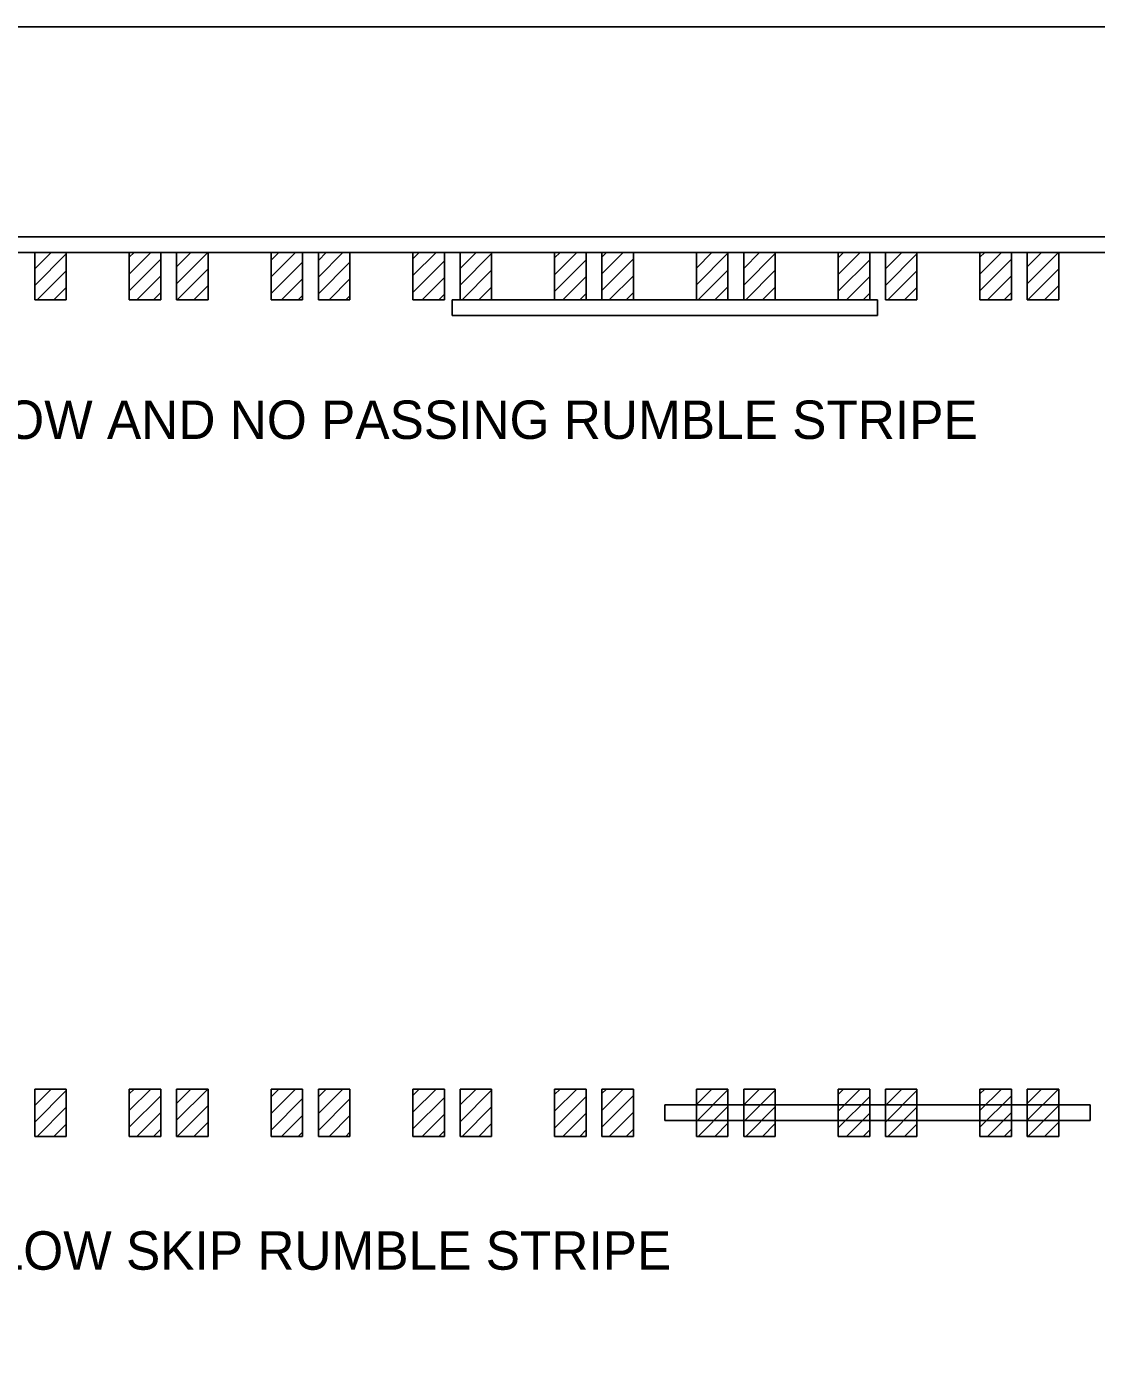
# Model space of a CAD drawing. Extents: x 49976.2 to 50021, y 49987.6 to 50011.4.
# Drawn here: x 50007.619 to 50009.846, y 49996.199 to 49998.999 of the extents above; entities that cross this region are included whole.
import ezdxf

# ---------------------------------------------------------------- set-up
doc = ezdxf.new("R2010")
doc.units = 0
doc.layers.add('Level 1', color=7, linetype='Continuous')
doc.layers.add('Level 2', color=7, linetype='Continuous')

msp = doc.modelspace()

# ---------------------------------------------------------------- linework, layer by layer
at = {"layer": 'Level 1'}
for p, q in [((50004.4031, 49998.5623), (50012.0505, 49998.5623)), ((50004.4031, 49998.5296), (50012.0505, 49998.5296)), ((50007.6358, 49998.4311), (50007.6358, 49998.5296)), ((50007.6358, 49998.5296), (50007.7014, 49998.5296)), ((50007.6358, 49998.4956), (50007.6697, 49998.5296)), ((50007.6358, 49998.4609), (50007.7014, 49998.5265)), ((50007.7014, 49998.5296), (50007.7014, 49998.4311)), ((50007.8326, 49998.4311), (50007.8326, 49998.5296)), ((50007.8326, 49998.5296), (50007.8982, 49998.5296)), ((50007.8326, 49998.4848), (50007.8773, 49998.5296)), ((50007.8326, 49998.5196), (50007.8425, 49998.5296)), ((50007.8326, 49998.45), (50007.8982, 49998.5156)), ((50007.8982, 49998.5296), (50007.8982, 49998.4311)), ((50007.931, 49998.4311), (50007.931, 49998.5296)), ((50007.931, 49998.5296), (50007.9966, 49998.5296)), ((50007.931, 49998.4647), (50007.9959, 49998.5296)), ((50007.931, 49998.4995), (50007.9611, 49998.5296)), ((50007.9966, 49998.5296), (50007.9966, 49998.4311)), ((50008.1278, 49998.4311), (50008.1278, 49998.5296)), ((50008.1278, 49998.5296), (50008.1934, 49998.5296)), ((50008.1278, 49998.4788), (50008.1786, 49998.5296)), ((50008.1278, 49998.5136), (50008.1438, 49998.5296)), ((50008.1278, 49998.444), (50008.1934, 49998.5096)), ((50008.1934, 49998.5296), (50008.1934, 49998.4311)), ((50008.2263, 49998.4311), (50008.2263, 49998.5296)), ((50008.2263, 49998.5296), (50008.2919, 49998.5296)), ((50008.2263, 49998.4784), (50008.2774, 49998.5296)), ((50008.2263, 49998.5132), (50008.2426, 49998.5296)), ((50008.2263, 49998.4436), (50008.2919, 49998.5092)), ((50008.2919, 49998.5296), (50008.2919, 49998.4311)), ((50008.4231, 49998.4311), (50008.4231, 49998.5296)), ((50008.4231, 49998.5296), (50008.4887, 49998.5296)), ((50008.4231, 49998.4814), (50008.4713, 49998.5296)), ((50008.4231, 49998.5162), (50008.4365, 49998.5296)), ((50008.4231, 49998.4466), (50008.4887, 49998.5122)), ((50008.4887, 49998.5296), (50008.4887, 49998.4311)), ((50008.5215, 49998.4311), (50008.5215, 49998.5296)), ((50008.5215, 49998.5296), (50008.5871, 49998.5296)), ((50008.5215, 49998.4965), (50008.5546, 49998.5296)), ((50008.5215, 49998.4617), (50008.5871, 49998.5273)), ((50008.5871, 49998.5296), (50008.5871, 49998.4311)), ((50008.7183, 49998.4311), (50008.7183, 49998.5296)), ((50008.7183, 49998.5296), (50008.7839, 49998.5296)), ((50008.7183, 49998.4834), (50008.7645, 49998.5296)), ((50008.7183, 49998.5182), (50008.7297, 49998.5296)), ((50008.7183, 49998.4486), (50008.7839, 49998.5142)), ((50008.7839, 49998.5296), (50008.7839, 49998.4311)), ((50008.8167, 49998.4311), (50008.8167, 49998.5296)), ((50008.8167, 49998.5296), (50008.8824, 49998.5296)), ((50008.8167, 49998.4853), (50008.861, 49998.5296)), ((50008.8167, 49998.5201), (50008.8262, 49998.5296)), ((50008.8167, 49998.4505), (50008.8824, 49998.5161)), ((50008.8824, 49998.5296), (50008.8824, 49998.4311)), ((50009.0136, 49998.4311), (50009.0136, 49998.5296)), ((50009.0136, 49998.5296), (50009.0792, 49998.5296)), ((50009.0136, 49998.4971), (50009.046, 49998.5296)), ((50009.0136, 49998.4623), (50009.0792, 49998.5279)), ((50009.0792, 49998.5296), (50009.0792, 49998.4311)), ((50009.112, 49998.4311), (50009.112, 49998.5296)), ((50009.112, 49998.5296), (50009.1776, 49998.5296)), ((50009.112, 49998.4965), (50009.145, 49998.5296)), ((50009.112, 49998.4617), (50009.1776, 49998.5273)), ((50009.1776, 49998.5296), (50009.1776, 49998.4311)), ((50009.3088, 49998.4311), (50009.3088, 49998.5296)), ((50009.3088, 49998.5296), (50009.3744, 49998.5296)), ((50009.3088, 49998.4837), (50009.3547, 49998.5296)), ((50009.3088, 49998.5185), (50009.3199, 49998.5296)), ((50009.3088, 49998.4489), (50009.3744, 49998.5145)), ((50009.3744, 49998.5296), (50009.3744, 49998.4311)), ((50009.4072, 49998.4311), (50009.4072, 49998.5296)), ((50009.4072, 49998.5296), (50009.4728, 49998.5296)), ((50009.4072, 49998.4956), (50009.4411, 49998.5296)), ((50009.4072, 49998.4609), (50009.4728, 49998.5265)), ((50009.4728, 49998.5296), (50009.4728, 49998.4311)), ((50009.6041, 49998.4311), (50009.6041, 49998.5296)), ((50009.6041, 49998.5296), (50009.6697, 49998.5296)), ((50009.6041, 49998.4848), (50009.6488, 49998.5296)), ((50009.6041, 49998.5196), (50009.614, 49998.5296)), ((50009.6041, 49998.45), (50009.6697, 49998.5156)), ((50009.6697, 49998.5296), (50009.6697, 49998.4311)), ((50009.7025, 49998.4311), (50009.7025, 49998.5296)), ((50009.7025, 49998.5296), (50009.7681, 49998.5296)), ((50009.7025, 49998.4647), (50009.7673, 49998.5296)), ((50009.7025, 49998.4995), (50009.7325, 49998.5296)), ((50009.7681, 49998.5296), (50009.7681, 49998.4311)), ((50007.6409, 49998.4311), (50007.7014, 49998.4917)), ((50007.8485, 49998.4311), (50007.8982, 49998.4808)), ((50007.9322, 49998.4311), (50007.9966, 49998.4955)), ((50008.1498, 49998.4311), (50008.1934, 49998.4748)), ((50008.2486, 49998.4311), (50008.2919, 49998.4745)), ((50008.4424, 49998.4311), (50008.4887, 49998.4774)), ((50008.5258, 49998.4311), (50008.5871, 49998.4925)), ((50008.7357, 49998.4311), (50008.7839, 49998.4794)), ((50008.8322, 49998.4311), (50008.8824, 49998.4813)), ((50009.0172, 49998.4311), (50009.0792, 49998.4931)), ((50009.1162, 49998.4311), (50009.1776, 49998.4925)), ((50009.3259, 49998.4311), (50009.3744, 49998.4797)), ((50009.4123, 49998.4311), (50009.4728, 49998.4917)), ((50009.62, 49998.4311), (50009.6697, 49998.4808)), ((50009.7037, 49998.4311), (50009.7681, 49998.4955)), ((50007.6756, 49998.4311), (50007.7014, 49998.4569)), ((50007.8833, 49998.4311), (50007.8982, 49998.4461)), ((50007.967, 49998.4311), (50007.9966, 49998.4607)), ((50008.5606, 49998.4311), (50008.5871, 49998.4577)), ((50008.867, 49998.4311), (50008.8824, 49998.4465)), ((50009.052, 49998.4311), (50009.0792, 49998.4583)), ((50009.151, 49998.4311), (50009.1776, 49998.4577)), ((50009.4471, 49998.4311), (50009.4728, 49998.4569)), ((50009.6548, 49998.4311), (50009.6697, 49998.4461)), ((50009.7385, 49998.4311), (50009.7681, 49998.4607)), ((50007.7014, 49998.4311), (50007.6358, 49998.4311)), ((50007.8982, 49998.4311), (50007.8326, 49998.4311)), ((50007.9966, 49998.4311), (50007.931, 49998.4311)), ((50008.1934, 49998.4311), (50008.1278, 49998.4311)), ((50008.1846, 49998.4311), (50008.1934, 49998.44)), ((50008.2919, 49998.4311), (50008.2263, 49998.4311)), ((50008.2834, 49998.4311), (50008.2919, 49998.4397)), ((50008.4887, 49998.4311), (50008.4231, 49998.4311)), ((50008.4772, 49998.4311), (50008.4887, 49998.4426)), ((50008.5051, 49998.4311), (50009.3908, 49998.4311)), ((50008.5051, 49998.4311), (50008.5051, 49998.3984)), ((50008.5871, 49998.4311), (50008.5215, 49998.4311)), ((50008.7839, 49998.4311), (50008.7183, 49998.4311)), ((50008.7705, 49998.4311), (50008.7839, 49998.4446)), ((50008.8824, 49998.4311), (50008.8167, 49998.4311)), ((50009.0792, 49998.4311), (50009.0136, 49998.4311)), ((50009.1776, 49998.4311), (50009.112, 49998.4311)), ((50009.3744, 49998.4311), (50009.3088, 49998.4311)), ((50009.3607, 49998.4311), (50009.3744, 49998.4449)), ((50009.3908, 49998.4311), (50009.3908, 49998.3984)), ((50009.4728, 49998.4311), (50009.4072, 49998.4311)), ((50009.6697, 49998.4311), (50009.6041, 49998.4311)), ((50009.7681, 49998.4311), (50009.7025, 49998.4311)), ((50008.5051, 49998.3984), (50009.3908, 49998.3984)), ((50007.6358, 49996.6898), (50007.6358, 49996.7882)), ((50007.6358, 49996.7882), (50007.7014, 49996.7882)), ((50007.6358, 49996.7543), (50007.6697, 49996.7882)), ((50007.6358, 49996.7195), (50007.7014, 49996.7851)), ((50007.7014, 49996.7882), (50007.7014, 49996.6898)), ((50007.8326, 49996.6898), (50007.8326, 49996.7882)), ((50007.8326, 49996.7882), (50007.8982, 49996.7882)), ((50007.8326, 49996.7435), (50007.8773, 49996.7882)), ((50007.8326, 49996.7783), (50007.8425, 49996.7882)), ((50007.8326, 49996.7087), (50007.8982, 49996.7743)), ((50007.8982, 49996.7882), (50007.8982, 49996.6898)), ((50007.931, 49996.6898), (50007.931, 49996.7882)), ((50007.931, 49996.7882), (50007.9966, 49996.7882)), ((50007.931, 49996.7234), (50007.9959, 49996.7882)), ((50007.931, 49996.7581), (50007.9611, 49996.7882)), ((50007.9966, 49996.7882), (50007.9966, 49996.6898)), ((50008.1278, 49996.6898), (50008.1278, 49996.7882)), ((50008.1278, 49996.7882), (50008.1934, 49996.7882)), ((50008.1278, 49996.7374), (50008.1786, 49996.7882)), ((50008.1278, 49996.7722), (50008.1438, 49996.7882)), ((50008.1278, 49996.7026), (50008.1934, 49996.7683)), ((50008.1934, 49996.7882), (50008.1934, 49996.6898)), ((50008.2263, 49996.6898), (50008.2263, 49996.7882)), ((50008.2263, 49996.7882), (50008.2919, 49996.7882)), ((50008.2263, 49996.7371), (50008.2774, 49996.7882)), ((50008.2263, 49996.7719), (50008.2426, 49996.7882)), ((50008.2263, 49996.7023), (50008.2919, 49996.7679)), ((50008.2919, 49996.7882), (50008.2919, 49996.6898)), ((50008.4231, 49996.6898), (50008.4231, 49996.7882)), ((50008.4231, 49996.7882), (50008.4887, 49996.7882)), ((50008.4231, 49996.74), (50008.4713, 49996.7882)), ((50008.4231, 49996.7748), (50008.4365, 49996.7882)), ((50008.4231, 49996.7053), (50008.4887, 49996.7709)), ((50008.4887, 49996.7882), (50008.4887, 49996.6898)), ((50008.5215, 49996.6898), (50008.5215, 49996.7882)), ((50008.5215, 49996.7882), (50008.5871, 49996.7882)), ((50008.5215, 49996.7551), (50008.5546, 49996.7882)), ((50008.5215, 49996.7203), (50008.5871, 49996.7859)), ((50008.5871, 49996.7882), (50008.5871, 49996.6898)), ((50008.7183, 49996.6898), (50008.7183, 49996.7882)), ((50008.7183, 49996.7882), (50008.7839, 49996.7882)), ((50008.7183, 49996.742), (50008.7645, 49996.7882)), ((50008.7183, 49996.7768), (50008.7297, 49996.7882)), ((50008.7183, 49996.7072), (50008.7839, 49996.7728)), ((50008.7839, 49996.7882), (50008.7839, 49996.6898)), ((50008.8167, 49996.6898), (50008.8167, 49996.7882)), ((50008.8167, 49996.7882), (50008.8824, 49996.7882)), ((50008.8167, 49996.7439), (50008.861, 49996.7882)), ((50008.8167, 49996.7787), (50008.8262, 49996.7882)), ((50008.8167, 49996.7091), (50008.8824, 49996.7747)), ((50008.8824, 49996.7882), (50008.8824, 49996.6898)), ((50009.0136, 49996.6898), (50009.0136, 49996.7882)), ((50009.0136, 49996.7882), (50009.0792, 49996.7882)), ((50009.0136, 49996.7558), (50009.046, 49996.7882)), ((50009.0136, 49996.721), (50009.0792, 49996.7866)), ((50009.0792, 49996.7882), (50009.0792, 49996.6898)), ((50009.112, 49996.6898), (50009.112, 49996.7882)), ((50009.112, 49996.7882), (50009.1776, 49996.7882)), ((50009.112, 49996.7552), (50009.145, 49996.7882)), ((50009.112, 49996.7204), (50009.1776, 49996.786)), ((50009.1776, 49996.7882), (50009.1776, 49996.6898)), ((50009.3088, 49996.6898), (50009.3088, 49996.7882)), ((50009.3088, 49996.7882), (50009.3744, 49996.7882)), ((50009.3088, 49996.7423), (50009.3547, 49996.7882)), ((50009.3088, 49996.7771), (50009.3199, 49996.7882)), ((50009.3088, 49996.7075), (50009.3744, 49996.7731)), ((50009.3744, 49996.7882), (50009.3744, 49996.6898)), ((50009.4072, 49996.6898), (50009.4072, 49996.7882)), ((50009.4072, 49996.7882), (50009.4728, 49996.7882)), ((50009.4072, 49996.7543), (50009.4411, 49996.7882)), ((50009.4072, 49996.7195), (50009.4728, 49996.7851)), ((50009.4728, 49996.7882), (50009.4728, 49996.6898)), ((50009.6041, 49996.6898), (50009.6041, 49996.7882)), ((50009.6041, 49996.7882), (50009.6697, 49996.7882)), ((50009.6041, 49996.7435), (50009.6488, 49996.7882)), ((50009.6041, 49996.7783), (50009.614, 49996.7882)), ((50009.6041, 49996.7087), (50009.6697, 49996.7743)), ((50009.6697, 49996.7882), (50009.6697, 49996.6898)), ((50009.7025, 49996.6898), (50009.7025, 49996.7882)), ((50009.7025, 49996.7882), (50009.7681, 49996.7882)), ((50009.7025, 49996.7234), (50009.7673, 49996.7882)), ((50009.7025, 49996.7581), (50009.7325, 49996.7882)), ((50009.7681, 49996.7882), (50009.7681, 49996.6898)), ((50007.6409, 49996.6898), (50007.7014, 49996.7503)), ((50007.8485, 49996.6898), (50007.8982, 49996.7395)), ((50007.9322, 49996.6898), (50007.9966, 49996.7542)), ((50008.5258, 49996.6898), (50008.5871, 49996.7511)), ((50008.7357, 49996.6898), (50008.7839, 49996.738)), ((50008.8322, 49996.6898), (50008.8824, 49996.7399)), ((50009.8337, 49996.7554), (50008.948, 49996.7554)), ((50008.948, 49996.7554), (50008.948, 49996.7226)), ((50009.0172, 49996.6898), (50009.0792, 49996.7518)), ((50009.1162, 49996.6898), (50009.1776, 49996.7512)), ((50009.3259, 49996.6898), (50009.3744, 49996.7383)), ((50009.4123, 49996.6898), (50009.4728, 49996.7503)), ((50009.62, 49996.6898), (50009.6697, 49996.7395)), ((50009.7037, 49996.6898), (50009.7681, 49996.7542)), ((50009.8337, 49996.7226), (50009.8337, 49996.7554)), ((50007.6756, 49996.6898), (50007.7014, 49996.7155)), ((50007.967, 49996.6898), (50007.9966, 49996.7194)), ((50008.1498, 49996.6898), (50008.1934, 49996.7335)), ((50008.2486, 49996.6898), (50008.2919, 49996.7331)), ((50008.4424, 49996.6898), (50008.4887, 49996.7361)), ((50008.5606, 49996.6898), (50008.5871, 49996.7163)), ((50008.948, 49996.7226), (50009.8337, 49996.7226)), ((50009.052, 49996.6898), (50009.0792, 49996.717)), ((50009.151, 49996.6898), (50009.1776, 49996.7164)), ((50009.4471, 49996.6898), (50009.4728, 49996.7155)), ((50009.7385, 49996.6898), (50009.7681, 49996.7194)), ((50007.7014, 49996.6898), (50007.6358, 49996.6898)), ((50007.8982, 49996.6898), (50007.8326, 49996.6898)), ((50007.8833, 49996.6898), (50007.8982, 49996.7047)), ((50007.9966, 49996.6898), (50007.931, 49996.6898)), ((50008.1934, 49996.6898), (50008.1278, 49996.6898)), ((50008.1846, 49996.6898), (50008.1934, 49996.6987)), ((50008.2919, 49996.6898), (50008.2263, 49996.6898)), ((50008.2834, 49996.6898), (50008.2919, 49996.6983)), ((50008.4887, 49996.6898), (50008.4231, 49996.6898)), ((50008.4772, 49996.6898), (50008.4887, 49996.7013)), ((50008.5871, 49996.6898), (50008.5215, 49996.6898)), ((50008.7839, 49996.6898), (50008.7183, 49996.6898)), ((50008.7705, 49996.6898), (50008.7839, 49996.7033)), ((50008.8824, 49996.6898), (50008.8167, 49996.6898)), ((50008.867, 49996.6898), (50008.8824, 49996.7051)), ((50009.0792, 49996.6898), (50009.0136, 49996.6898)), ((50009.1776, 49996.6898), (50009.112, 49996.6898)), ((50009.3744, 49996.6898), (50009.3088, 49996.6898)), ((50009.3607, 49996.6898), (50009.3744, 49996.7035)), ((50009.4728, 49996.6898), (50009.4072, 49996.6898)), ((50009.6697, 49996.6898), (50009.6041, 49996.6898)), ((50009.6548, 49996.6898), (50009.6697, 49996.7047)), ((50009.7681, 49996.6898), (50009.7025, 49996.6898))]:
    msp.add_line(p, q, dxfattribs=at)
msp.add_lwpolyline([(49999.3835, 49998.9992), (50016.7501, 49998.9992), (50016.7501, 49987.7988), (49999.3835, 49987.7988)], close=True, dxfattribs=at)

# ---------------------------------------------------------------- texts
at = {"layer": 'Level 2'}
for s, height, p in [('DOUBLE YELLOW AND NO PASSING RUMBLE STRIPE', 0.080012, (50006.8407, 49998.1415)), ('YELLOW SKIP RUMBLE STRIPE', 0.08, (50007.3501, 49996.4122))]:
    msp.add_text(s, height=height, dxfattribs=at).set_placement(p)

doc.saveas('drawing.dxf')
